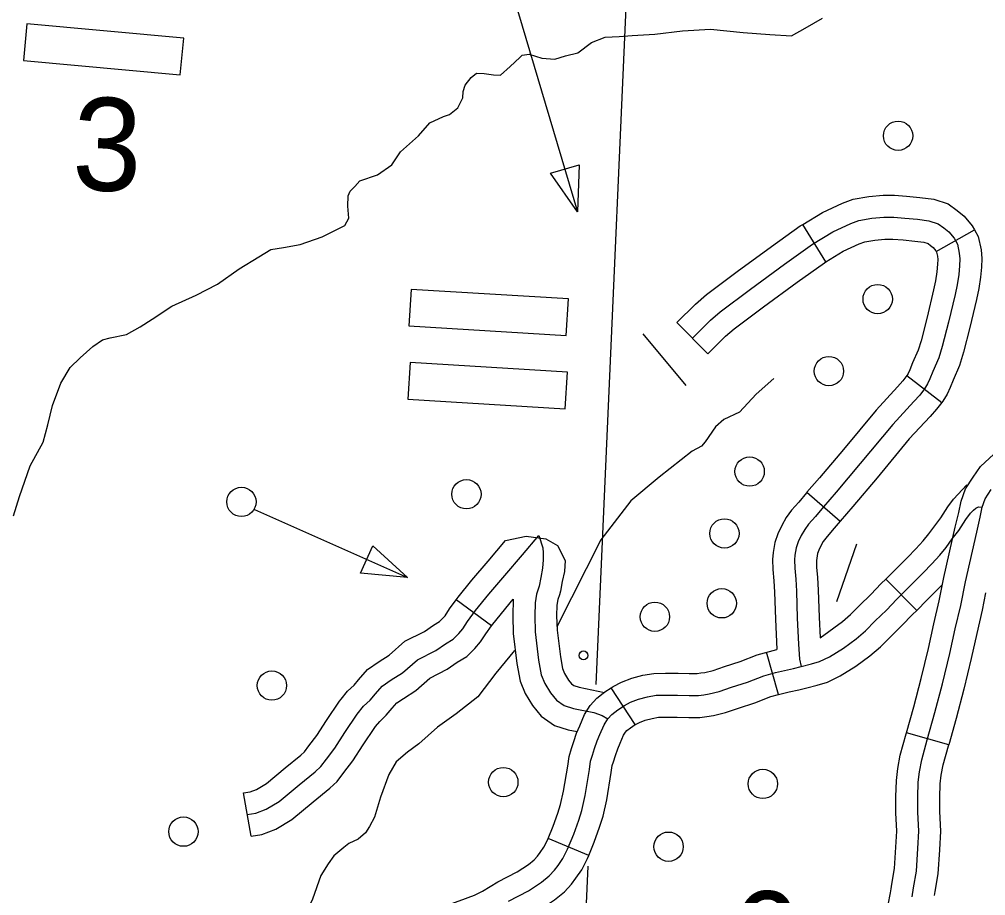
# Model space of a CAD drawing. Extents: x 653372 to 905732, y 627442 to 787275.
# Drawn here: x 708783 to 712080, y 753334 to 756322 of the extents above; entities that cross this region are included whole.
import ezdxf

# ---------------------------------------------------------------- set-up
doc = ezdxf.new("R2010")
doc.units = 0
for name, color, linetype in [('31', 7, 'Continuous'), ('32', 7, 'Continuous'), ('35', 7, 'Continuous'), ('45', 7, 'Continuous'), ('5', 7, 'Continuous'), ('56', 7, 'Continuous'), ('57', 7, 'Continuous')]:
    doc.layers.add(name, color=color, linetype=linetype)

msp = doc.modelspace()

# ---------------------------------------------------------------- linework, layer by layer
at = {"layer": '31'}
for q in [(711809.8, 753889.3), (711954.1, 753848.4)]:
    msp.add_line((711954.1, 753848.4), q, dxfattribs=at)
for points in [[(711933.1, 754396.4), (711937.7, 754419.3), (711976.7, 754590.5), (711988.4, 754640.8), (711996.3, 754679.2), (712011.5, 754721.3), (712037.5, 754760.8), (712062.9, 754797), (712093, 754825.4), (712131.4, 754860.8), (712180.8, 754894.4), (712191.4, 754900.6)], [(712079, 754687.5), (712099.5, 754718.6)], [(711829.2, 753329.9), (711834.1, 753360.9), (711843.9, 753417.2), (711848.9, 753494.6), (711852.1, 753553.8), (711848.6, 753618.7), (711848.8, 753669.9), (711850.3, 753721.1), (711854.8, 753756.7), (711862, 753796.9), (711881, 753865.3), (711907.3, 753958.2), (711933.2, 754055.9), (711957.9, 754159.6), (711976.6, 754244), (711995.1, 754323.8), (712011, 754403.6), (712049.8, 754573.7), (712061.6, 754624.7), (712068.7, 754658.9), (712079, 754687.5)], [(711809.8, 753889.3), (711835, 753978), (711860.4, 754074.1), (711884.8, 754176.4), (711903.4, 754260.6), (711921.8, 754339.7), (711933.1, 754396.4)], [(712080.2, 754367.1), (712068.5, 754308), (712049.7, 754227.4), (712031, 754142.8), (712005.9, 754037.6), (711979.7, 753938.4), (711954.1, 753848.4)], [(711757.7, 753357.8), (711760.2, 753373.2), (711769.3, 753426.1), (711774.1, 753499), (711776.9, 753553.8), (711773.6, 753616.8), (711773.8, 753671.2), (711775.5, 753726.9), (711780.6, 753768), (711788.9, 753813.6), (711808.7, 753885.5), (711809.8, 753889.3)], [(711905.8, 753334), (711908.1, 753348.5), (711918.5, 753408.3), (711923.8, 753490.2), (711927.2, 753553.8), (711923.6, 753620.5), (711923.8, 753668.6), (711925.2, 753715.3), (711928.9, 753745.4), (711935.2, 753780.2), (711953.2, 753845), (711954.1, 753848.4)], [(711690.2, 752842.9), (711711.6, 752930.6), (711726.1, 752983.6), (711730.3, 753008.7), (711737.4, 753051.1), (711740.3, 753074.9), (711740.1, 753107.5), (711740, 753150.7), (711739.8, 753187.8), (711738.9, 753231.3), (711741.7, 753266.9), (711747.4, 753302.8), (711755.3, 753343.1), (711757.7, 753357.8)]]:
    msp.add_lwpolyline(points, dxfattribs=at)
at = {"layer": '32'}
for p, q in [((711534.6, 755494.8), (711456.3, 755622.7)), ((711911.5, 755530.6), (712042.4, 755603.9)), ((711132.6, 755181.7), (711026.8, 755288)), ((711811.6, 755107.2), (711930.2, 755015.4)), ((711470.6, 754709.6), (711584.1, 754611.5)), ((711845.1, 754306.9), (711739.1, 754412.9)), ((711373, 754019.7), (711332.8, 754164.2)), ((710884.6, 753917.1), (710802.5, 754042.6)), ((710725.8, 753471.1), (710587.5, 753529.1))]:
    msp.add_line(p, q, dxfattribs=at)
for points in [[(711456.3, 755622.7), (711523.1, 755663.7), (711592.1, 755695.3), (711628.1, 755708.4), (711682, 755718.4), (711730.4, 755722.4), (711769.7, 755722.1), (711810.4, 755719.4), (711856, 755715.1), (711903.4, 755708.8), (711952.1, 755692.7), (711983, 755670.7), (712007.2, 755651.2), (712034.5, 755618), (712042.4, 755603.9)], [(711079.7, 755234.9), (711141.5, 755296.4), (711174.7, 755325), (711277.5, 755402.2), (711393.5, 755487), (711489.2, 755555), (711558.4, 755597.4), (711620.6, 755625.8), (711647.9, 755635.8), (711691.9, 755643.9), (711733.1, 755647.4), (711766.8, 755647.1), (711804.5, 755644.6), (711847.5, 755640.6), (711886.5, 755635.4), (711917.8, 755625), (711937.6, 755610.9), (711954.1, 755597.6), (711972.3, 755575.5), (711983.8, 755554.9), (711990.3, 755525.3), (711991.7, 755505), (711991, 755482.1), (711988.1, 755451.8), (711983, 755416.9), (711976, 755383.4), (711952.9, 755289.1), (711932.2, 755206.7), (711921, 755168), (711900, 755121.2), (711889.8, 755096.6), (711881.9, 755079.3), (711872, 755062.7), (711855.1, 755041), (711834.9, 755018.6), (711763.1, 754940.6), (711652.3, 754807.1), (711569.8, 754709.8), (711526.6, 754659.7), (711500, 754627.4), (711476.2, 754600.5), (711462.9, 754582.7), (711450.8, 754561.5), (711440.7, 754540.3), (711434.1, 754519.6), (711429.3, 754494.8), (711428.1, 754478.6), (711428.6, 754450.3), (711432.2, 754413.1), (711434.4, 754372.6), (711437.6, 754280.1), (711441.7, 754191.6), (711445.6, 754140.3), (711451.2, 754115.8)], [(711026.8, 755288), (711090.5, 755351.4), (711127.7, 755383.5), (711232.8, 755462.5), (711349.6, 755547.9), (711447.9, 755617.6), (711456.3, 755622.7)], [(712042.4, 755603.9), (712054.7, 755581.9), (712064.8, 755536), (712066.8, 755506.5), (712065.9, 755477.4), (712062.6, 755442.8), (712056.9, 755403.8), (712049.1, 755366.8), (712025.7, 755271), (712004.6, 755187.1), (711991.5, 755142.1), (711968.9, 755091.6), (711958.6, 755066.6), (711948.3, 755044.2), (711934, 755020.3), (711930.2, 755015.4)], [(711534.6, 755494.8), (711593.8, 755531.1), (711649.1, 755556.4), (711667.7, 755563.2), (711701.9, 755569.5), (711735.9, 755572.4), (711764, 755572.1), (711798.6, 755569.8), (711839.1, 755566.1), (711869.6, 755562), (711883.6, 755557.4), (711892.3, 755551.2), (711901, 755544.1), (711910.1, 755533), (711911.5, 755530.6)], [(711911.5, 755530.6), (711912.9, 755528), (711915.9, 755514.5), (711916.7, 755503.5), (711916.2, 755486.8), (711913.6, 755460.9), (711909.2, 755430.1), (711902.8, 755400.1), (711880.1, 755307.1), (711859.8, 755226.4), (711850.4, 755193.9), (711831.1, 755150.8), (711821.1, 755126.5), (711815.5, 755114.3), (711809.9, 755105.1), (711811.6, 755107.2)], [(711132.6, 755181.7), (711192.5, 755241.3), (711221.8, 755266.6), (711322.1, 755341.9), (711437.3, 755426.2), (711530.5, 755492.3), (711534.6, 755494.8)], [(711811.6, 755107.2), (711797.6, 755089.2), (711779.5, 755069.2), (711706.6, 754989.9), (711594.8, 754855.3), (711512.9, 754758.5), (711470.6, 754709.6)], [(711930.2, 755015.4), (711912.7, 754992.8), (711890.3, 754968.1), (711819.6, 754891.2), (711709.8, 754758.9), (711626.8, 754661), (711584.1, 754611.5)], [(711470.6, 754709.6), (711469.3, 754708.1), (711442.9, 754676.1), (711418, 754647.9), (711400.1, 754624), (711384.3, 754596.2), (711370.9, 754568), (711361.3, 754538.3), (711354.8, 754504.6), (711353.1, 754480.6), (711353.7, 754446), (711357.4, 754407.5), (711359.4, 754369.2), (711362.7, 754277), (711367.5, 754173.8)], [(711739.1, 754412.9), (711773.9, 754447.8), (711813.3, 754487.1), (711842.4, 754516.8), (711866.7, 754543.9), (711885.9, 754567.2), (711906.4, 754595.3), (711927.4, 754622.5), (711951.1, 754659.6), (711970.7, 754686), (712016.2, 754734.6)], [(710452.5, 753315), (710520.3, 753350.1), (710565, 753379.8), (710591.2, 753401.2), (710609.4, 753420.9), (710621.3, 753437.4), (710637.5, 753460.2), (710653.3, 753492.1), (710675.1, 753544), (710692, 753591.4), (710702.4, 753624.8), (710714.1, 753675.7), (710728.9, 753764.7), (710732.4, 753792.9), (710738.4, 753813), (710745.8, 753835.7), (710754.7, 753861.7), (710764.1, 753883.7), (710778.6, 753916.5), (710791.3, 753937.1), (710805, 753952.2), (710825, 753967.7), (710847.7, 753982.6), (710868.3, 753993.4), (710896.2, 754004), (710926.1, 754011.9), (710955.9, 754017.1), (710988.3, 754018.1), (711029.4, 754017.6), (711068.5, 754016.4), (711100.8, 754016.8), (711119.1, 754018.9), (711137.4, 754021.7), (711171.3, 754030.2), (711212.9, 754044.4), (711267.3, 754062), (711323.9, 754083.9), (711363.3, 754094.9), (711393.9, 754102), (711425.1, 754108.5), (711451.2, 754115.8), (711486.5, 754124.2), (711513.7, 754132.2), (711547.2, 754148.7), (711595.3, 754178.2), (711638, 754210), (711670.5, 754237.3), (711703.2, 754270.8), (711741.4, 754308), (711777.6, 754345.4), (711826.9, 754394.7), (711866.5, 754434.3), (711897.1, 754465.4), (711923.6, 754495), (711945.3, 754521.3), (711966.4, 754550.3), (711988.8, 754579.3), (712012.9, 754617), (712028.3, 754637.8), (712038.8, 754649), (712046.3, 754654.8), (712055.2, 754659.3), (712068.7, 754658.9)], [(711584, 754611.5), (711583.9, 754611.3), (711557, 754578.7), (711534.5, 754553.2), (711525.7, 754541.5), (711517.4, 754526.9), (711510.6, 754512.6), (711506.8, 754500.8), (711503.7, 754484.9), (711503.1, 754476.6), (711503.5, 754454.6), (711507, 754418.7), (711509.3, 754375.9), (711512.6, 754283.2), (711515.8, 754212.7)], [(711515.8, 754212.7), (711591.5, 754268.9), (711619.5, 754292.4), (711650.2, 754323.8), (711688.2, 754361), (711724.1, 754398), (711739.1, 754412.9)], [(711845.1, 754306.9), (711879.9, 754341.7), (711932.7, 754394.5)], [(711373, 754019.7), (711382, 754022.2), (711410.1, 754028.8), (711442.8, 754035.6), (711470, 754043.2), (711505.7, 754051.7), (711541, 754062), (711583.5, 754083), (711637.4, 754116.1), (711684.6, 754151.2), (711721.6, 754182.3), (711756.2, 754217.7), (711794.5, 754255.1), (711831, 754292.8), (711845.1, 754306.9)], [(710802.5, 754042.6), (710809.6, 754047.3), (710837.3, 754061.9), (710873.3, 754075.6), (710910.1, 754085.3), (710948.3, 754091.9), (710987.6, 754093.1), (711031, 754092.6), (711069.1, 754091.4), (711096, 754091.7), (711109, 754093.3), (711122.6, 754095.4), (711150.1, 754102.2), (711189.2, 754115.6), (711242.2, 754132.7), (711300.3, 754155.2), (711367.5, 754173.8)], [(710587.5, 753529.1), (710605.1, 753571.2), (710620.9, 753615.2), (710630, 753644.4), (710640.5, 753690.2), (710654.6, 753775.5), (710658.8, 753808.4), (710666.8, 753835.4), (710674.7, 753859.4), (710684.6, 753888.6), (710695.3, 753913.5), (710712.1, 753951.6), (710731.2, 753982.4), (710753.8, 754007.3), (710781.4, 754028.8), (710802.5, 754042.6)], [(710884.6, 753917.1), (710885.8, 753917.9), (710899.2, 753924.9), (710919.1, 753932.5), (710942.1, 753938.6), (710963.6, 753942.3), (710989, 753943.1), (711027.8, 753942.6), (711067.8, 753941.4), (711105.6, 753941.8), (711129.2, 753944.6), (711152.1, 753948.1), (711192.6, 753958.2), (711236.6, 753973.3), (711292.4, 753991.3), (711347.5, 754012.6), (711373, 754019.7)], [(710725.8, 753471.1), (710745, 753516.9), (710763.1, 753567.6), (710774.9, 753605.2), (710787.7, 753661.1), (710803.1, 753753.9), (710806.1, 753777.4), (710810, 753790.6), (710817, 753811.9), (710824.8, 753834.8), (710832.9, 753853.8), (710845.1, 753881.5), (710851.5, 753891.7), (710856.2, 753897), (710868.6, 753906.7), (710884.6, 753917.1)], [(710211.9, 753293.7), (710240.1, 753299.9), (710283.8, 753316.3), (710335.9, 753335.4), (710363.9, 753349.5), (710416, 753380.6), (710482.2, 753414.8), (710520.4, 753440.2), (710539.7, 753455.9), (710551.2, 753468.5), (710560.4, 753481.1), (710572.9, 753498.8), (710585, 753523.2), (710587.5, 753529.1)], [(710244.4, 753147.2), (710282.8, 753155.8), (710336, 753175.6), (710395.7, 753197.6), (710436.1, 753217.9), (710489, 753249.5), (710558.4, 753285.3), (710609.6, 753319.3), (710642.8, 753346.5), (710667.5, 753373.3), (710682.3, 753393.7), (710702.1, 753421.6), (710721.5, 753460.9), (710725.8, 753471.1)]]:
    msp.add_lwpolyline(points, dxfattribs=at)
at = {"layer": '35'}
for points in [[(710490.4, 756192.1), (710498.6, 756199.8), (710522.6, 756203.1), (710566.1, 756189.8), (710609.9, 756186.5), (710646.2, 756197.4), (710688.4, 756208.1), (710735.4, 756242.6), (710781.9, 756261.2), (710829.8, 756263.7), (710873.8, 756266.4), (710951.9, 756272), (711045.4, 756282.9), (711141.4, 756288), (711252.8, 756276.7), (711344.4, 756269.9), (711418.2, 756265.7), (711464.9, 756292.3), (711523.8, 756326.4)], [(708763.6, 754628.9), (708784.4, 754695.3), (708820.5, 754799.5), (708864.9, 754880.1), (708880.6, 754939.5), (708896.5, 755004.9), (708924.8, 755081.9), (708956.3, 755134.9), (708991.3, 755167.8), (709034.3, 755206.5), (709067, 755229.4), (709093.1, 755236.6), (709149.3, 755246.9), (709196, 755273.5), (709236.8, 755300.2), (709304, 755344.1), (709386.9, 755381.6), (709459.9, 755419.3), (709533.3, 755470.8), (709600.4, 755512.7), (709641.1, 755537.4), (709685.2, 755544.1), (709741.4, 755554.4), (709816.1, 755580.1), (709868.7, 755606.5), (709894.3, 755618.9), (709907, 755644.5), (709904.2, 755684.5), (709905.3, 755720.4), (709911.8, 755736.2), (709928.2, 755751.7), (709944.8, 755771.1), (710005.2, 755791.3), (710054.2, 755825.8), (710083.5, 755870.8), (710145, 755924.9), (710184.3, 755969.6), (710230.8, 755990.2), (710251, 755997.6), (710279.6, 756020.7), (710296.6, 756054.1), (710297.2, 756076.1), (710303.9, 756097.8), (710324.6, 756123.2), (710343, 756138.6), (710369, 756137.8), (710400.7, 756132.8), (710424.7, 756132.1), (710457.5, 756161.1), (710490.4, 756192.1)], [(711357.9, 755097.8), (711297.8, 755044.3), (711240.1, 754982.2), (711187.4, 754957.8), (711158.7, 754932.7), (711123.3, 754881.8), (711110.8, 754866.2), (711078.4, 754849.2), (710966, 754760.8), (710869.7, 754679.8), (710767.6, 754547.6), (710617.1, 754250.1)], [(710472.4, 754170.4), (710408.9, 754092.6), (710347.2, 754011.9), (710273.6, 753954.2), (710210.4, 753908.1), (710146.8, 753852.1), (710108, 753823.4), (710069.1, 753790.6), (710043.9, 753747.4), (710015.6, 753670.4), (709995.6, 753601.1), (709978.6, 753569.7), (709964, 753548.1), (709939.4, 753526.9), (709907, 753511.9), (709890.7, 753498.4), (709855.9, 753469.5), (709837.1, 753442.1), (709812, 753402.9), (709783.6, 753321.9), (709769.9, 753292.4), (709725.8, 753256.5)]]:
    msp.add_lwpolyline(points, dxfattribs=at)
at = {"layer": '45'}
for p, q in [((710394.3, 754253.5), (710273.6, 754342.5)), ((709573.8, 753536.3), (709548.2, 753684.1))]:
    msp.add_line(p, q, dxfattribs=at)
for points in [[(709561, 753610.2), (709590.4, 753615.3), (709625.3, 753628.7), (709670, 753655.4), (709737.8, 753712.3), (709793.1, 753756.7), (709811.6, 753774.1), (709831, 753799.4), (709859.5, 753836.7), (709894.2, 753890.3), (709936.3, 753952.3), (709958, 753979.7), (709980.9, 754000.6), (709998.4, 754022.1), (710021.5, 754048.7), (710052.3, 754069.4), (710090.4, 754094.1), (710141.4, 754138.6), (710204.2, 754170.4), (710237.2, 754193.2), (710263.5, 754208.9), (710282.8, 754227.8), (710296.2, 754243.9), (710312.8, 754269.3), (710339.8, 754305.9), (710385.1, 754361.8), (710440.2, 754425.6), (710499.5, 754496.2), (710556.1, 754561.6)], [(710273.6, 754342.5), (710280.4, 754351.8), (710327.6, 754409.9), (710383.1, 754474.2), (710442.4, 754544.9), (710512.1, 754559.6), (710579.1, 754551.1), (710620, 754527.5), (710646.1, 754476.6), (710643.1, 754439.7), (710635.7, 754404.8), (710629.9, 754372), (710626, 754359.7)], [(710556.1, 754561.6), (710569.4, 754520.3), (710570.3, 754503), (710571.1, 754478.6), (710568.8, 754450.6), (710562.1, 754419.2), (710556.9, 754389.8), (710548.1, 754361.8), (710542.9, 754332.5), (710541.6, 754288), (710543.6, 754233.2), (710555, 754136.5), (710564.3, 754086.6), (710576.4, 754057.5), (710595.6, 754026), (710615.7, 754000.9), (710642.4, 753982.2), (710674.5, 753972.6), (710743.1, 753958.3), (710771.5, 753948.1), (710791.3, 753937.1)], [(710626, 754359.7), (710621.1, 754344), (710617.7, 754324.8), (710616.6, 754288.2), (710618.4, 754239), (710629.2, 754147.8), (710636.6, 754108.1), (710643.5, 754091.6), (710657.1, 754069.1), (710667.5, 754056.2), (710675.6, 754050.5), (710692.9, 754045.3), (710779.5, 754027.3)], [(709881.3, 754003.7), (709902.9, 754031), (709926.2, 754052.3), (709941, 754070.4), (709971.4, 754105.4), (710011, 754132), (710045.1, 754154.1), (710099.1, 754201.3), (710165.8, 754235.1), (710196.6, 754256.3), (710217.4, 754268.8), (710227.6, 754278.7), (710235.8, 754288.5), (710251.2, 754312.1), (710273.6, 754342.5)], [(710394.3, 754253.5), (710399.1, 754260), (710468.3, 754345.3)], [(710468.3, 754345.3), (710466.6, 754287.7), (710468.7, 754227.5), (710480.8, 754125.2), (710492, 754065.2), (710509.3, 754023.4), (710534, 753982.9), (710563.8, 753945.7), (710609.3, 753913.8), (710656, 753899.8), (710686.3, 753893.5)], [(709999, 753910.7), (710013, 753928.4), (710035.5, 753948.9), (710055.8, 753973.8), (710071.6, 753992), (710093.6, 754006.8), (710135.7, 754034.1), (710183.6, 754076), (710242.5, 754105.8), (710277.7, 754130), (710309.6, 754149.1), (710338, 754176.9), (710356.6, 754199.3), (710374.4, 754226.5), (710394.3, 754253.5)], [(709548.2, 753684.1), (709570.5, 753688), (709592.5, 753696.4), (709626.4, 753716.7), (709690.3, 753770.3), (709743.8, 753813.3), (709755.8, 753824.6), (709771.5, 753845), (709798.1, 753879.9), (709831.6, 753931.7), (709875.8, 753996.7), (709881.3, 754003.7)], [(709573.8, 753536.3), (709610.4, 753542.7), (709658.2, 753560.9), (709713.6, 753594.1), (709785.4, 753654.3), (709842.4, 753700.1), (709867.4, 753723.6), (709890.6, 753753.8), (709920.9, 753793.5), (709956.7, 753848.8), (709996.8, 753907.9), (709999, 753910.7)]]:
    msp.add_lwpolyline(points, dxfattribs=at)
at = {"layer": '5'}
for points in [[(710892.9, 757262.5), (710750.3, 754053.8)], [(710722.8, 753434.7), (710658.6, 751990.5)]]:
    msp.add_lwpolyline(points, dxfattribs=at)
at = {"layer": '56'}
for p, q in [((710595.5, 755797.4), (710693.2, 755826.5)), ((710688, 755665.3), (710595.5, 755797.4)), ((710693.2, 755826.5), (710688, 755665.3)), ((709947.6, 754434), (709989, 754527.2)), ((709989, 754527.2), (710108.1, 754418.4)), ((710108.1, 754418.4), (709947.6, 754434))]:
    msp.add_line(p, q, dxfattribs=at)
for points in [[(710162.4, 756855), (710429.3, 756534.3), (710688, 755665.3)], [(710910.4, 755250.1), (711057.3, 755073.6)], [(709586.3, 754650.5), (710108.1, 754418.4)], [(711639.8, 754532.4), (711571.1, 754336)]]:
    msp.add_lwpolyline(points, dxfattribs=at)
for centre, radius in [((711781.3, 755924.9), 50), ((711711.8, 755368.2), 50), ((711545.5, 755122.5), 50), ((711275, 754780.2), 50), ((710308.8, 754702.7), 50), ((709541.2, 754676.7), 50), ((711188.9, 754569.1), 50), ((711179.9, 754330.8), 50), ((710951.9, 754284.8), 50), ((710708, 754153.3), 15), ((709645, 754050.2), 50), ((710434.6, 753721.1), 50), ((711320, 753715), 50), ((709343.3, 753552.3), 50), ((710998.5, 753501), 50)]:
    msp.add_circle(centre, radius, dxfattribs=at)
at = {"layer": '57'}
for p, q in [((708808.8, 756306.5), (708797.4, 756182)), ((709344.1, 756257.4), (708808.8, 756306.5)), ((709332.7, 756133), (709344.1, 756257.4)), ((708797.4, 756182), (709332.7, 756133)), ((710120.2, 755401.4), (710112.7, 755276.6)), ((710656.7, 755369.3), (710120.2, 755401.4)), ((710649.3, 755244.5), (710656.7, 755369.3)), ((710112.7, 755276.6), (710649.3, 755244.5)), ((710116.8, 755151.4), (710109.4, 755026.6)), ((710653.4, 755119.3), (710116.8, 755151.4)), ((710645.9, 754994.5), (710653.4, 755119.3)), ((710109.4, 755026.6), (710645.9, 754994.5))]:
    msp.add_line(p, q, dxfattribs=at)

# ---------------------------------------------------------------- texts
at = {"layer": '56'}
msp.add_text('6', height=316.8, rotation=358.28, dxfattribs=at).set_placement((711202.7, 753036.1))
at = {"layer": '57'}
msp.add_text('3', height=316.8, rotation=358.28, dxfattribs=at).set_placement((708961.2, 755741.1))

doc.saveas('drawing.dxf')
